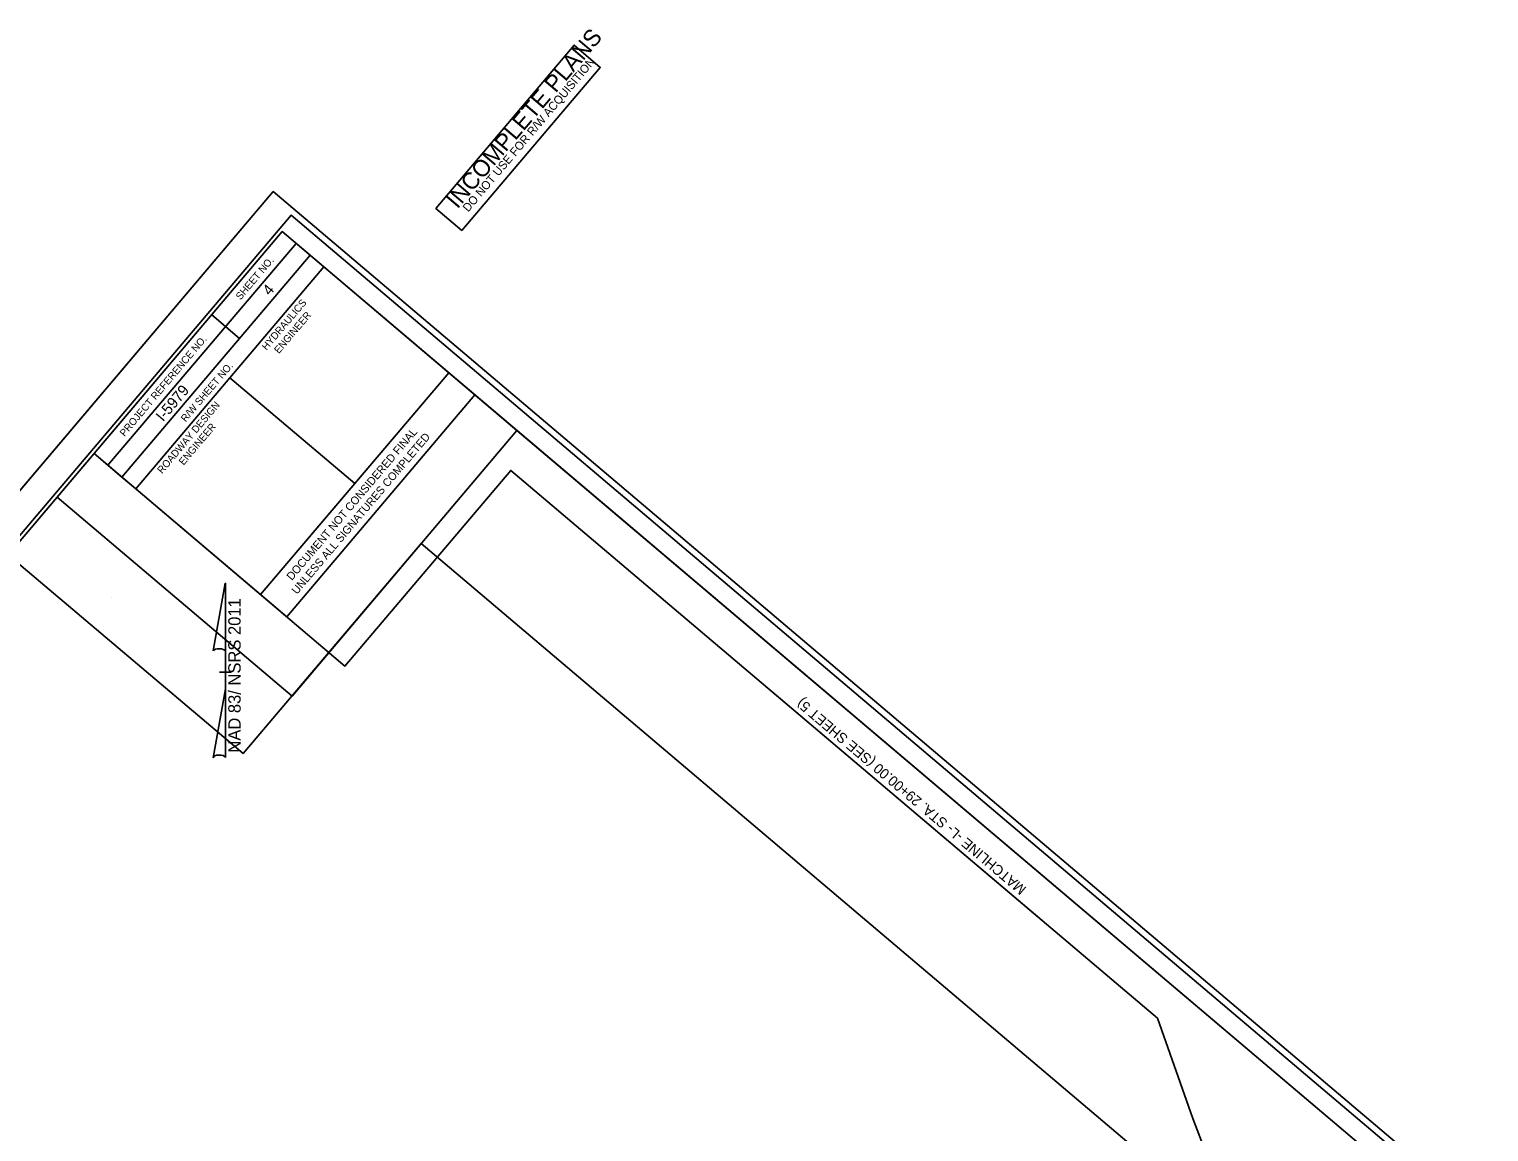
# Model space of a CAD drawing. Extents: x 1761000 to 1762924, y 421789 to 423893.
# Drawn here: x 1761921 to 1762924, y 423135 to 423893 of the extents above; entities that cross this region are included whole.
import ezdxf

# ---------------------------------------------------------------- set-up
doc = ezdxf.new("R2010")
doc.units = 0
for name, color, linetype in [('CTL Primary Horizontal and Vertical Cogo Number', 7, 'Continuous'), ('CTL Sheet Datum Description CELL', 7, 'Continuous'), ('Exist Hydro Stream or Body of Water', 7, 'Continuous'), ('Exist Other Culture Sign Post CELL', 7, 'Continuous'), ('Exist Roads Change in Surface', 7, 'Continuous'), ('Exist Roads Change in Surface Leader', 7, 'Continuous'), ('Exist Roads Change in Surface Text', 7, 'Continuous'), ('Exist Roads Curbs', 7, 'Continuous'), ('Exist Roads Curbs Leader', 7, 'Continuous'), ('Exist Roads EOP', 7, 'Continuous'), ('Exist Roads EOP Other', 7, 'Continuous'), ('Exist Roads EOP Text', 7, 'Continuous'), ('Exist Roads Soil', 7, 'Continuous'), ('Exist Structure Major Deck Tunnel Box Culvert', 7, 'Continuous')]:
    doc.layers.add(name, color=color, linetype=linetype)

msp = doc.modelspace()

# ---------------------------------------------------------------- linework, layer by layer
at = {"layer": 'CTL Primary Horizontal and Vertical Cogo Number'}
msp.add_lwpolyline([(1761925, 421929.5), (1762829.9, 422997.7), (1762190.1, 423539.7), (1762067.8, 423395.3), (1761906.4, 423532), (1761123.8, 422608.2)], close=True, dxfattribs=at)
at = {"layer": 'CTL Sheet Datum Description CELL'}
msp.add_lwpolyline([(1761931.8, 421937.6), (1762821.5, 422987.8), (1762733.1, 423111.6), (1762720.6, 423144.4), (1762696.3, 423213.4), (1762251.7, 423590), (1762137.8, 423455.5), (1761965.3, 423601.6), (1761130.7, 422616.3)], close=True, dxfattribs=at)
at = {"layer": 'Exist Other Culture Sign Post CELL'}
msp.add_line((1762614.2, 423282.9), (1762431.1, 423438.1), dxfattribs=at)
at = {"layer": 'Exist Roads Change in Surface'}
msp.add_lwpolyline([(1761835.8, 421789.4), (1762924, 423073.9), (1762088.5, 423781.7), (1761000.3, 422497.2)], close=True, dxfattribs=at)
at = {"layer": 'Exist Roads Change in Surface Leader'}
msp.add_lwpolyline([(1762218.2, 423754.9), (1762200.3, 423770.1), (1762295.3, 423882.3), (1762313.2, 423867.1)], close=True, dxfattribs=at)
at = {"layer": 'Exist Roads Change in Surface Text'}
msp.add_line((1762088.5, 423781.7), (1761000.3, 422497.2), dxfattribs=at)
at = {"layer": 'Exist Roads Curbs Leader'}
msp.add_line((1761977, 423502.5), (1761977, 423502.5), dxfattribs=at)
at = {"layer": 'Exist Roads EOP'}
for p, q in [((1762079.8, 423504.6), (1762209.1, 423657.2)), ((1762079.8, 423504.6), (1762209.1, 423657.2)), ((1762209.1, 423657.2), (1762227.1, 423642)), ((1762209.1, 423657.2), (1762227.1, 423642)), ((1762227.1, 423642), (1762097.8, 423489.4)), ((1762227.1, 423642), (1762097.8, 423489.4)), ((1762097.8, 423489.4), (1762079.8, 423504.6)), ((1762097.8, 423489.4), (1762079.8, 423504.6))]:
    msp.add_line(p, q, dxfattribs=at)
at = {"layer": 'Exist Roads EOP Other'}
for p, q in [((1761974.9, 423593.5), (1762104.2, 423746.1)), ((1761984.5, 423585.4), (1762113.8, 423738)), ((1761984.5, 423585.4), (1762113.8, 423738)), ((1762046.2, 423696.9), (1762065.3, 423680.8)), ((1762058.7, 423653.6), (1762144.5, 423580.9)), ((1761984.5, 423585.4), (1761994, 423577.3))]:
    msp.add_line(p, q, dxfattribs=at)
for points in [[(1762094.7, 423754.2), (1761125.1, 422609.7), (1761926.2, 421931), (1762895.8, 423075.5)], [(1761965.3, 423601.6), (1762094.7, 423754.2), (1762113.8, 423738), (1761984.5, 423585.4)], [(1762058.7, 423653.6), (1762123.3, 423729.9), (1762209.1, 423657.2), (1762144.5, 423580.9)], [(1761926.2, 421931), (1761125.1, 422609.6), (1761965.3, 423601.6), (1762079.8, 423504.6), (1762209.1, 423657.2), (1762895.8, 423075.5)], [(1761994, 423577.3), (1762058.7, 423653.6), (1762144.5, 423580.9), (1762079.8, 423504.6)]]:
    msp.add_lwpolyline(points, close=True, dxfattribs=at)
at = {"layer": 'Exist Roads EOP Text'}
for p, q in [((1762047.3, 423466), (1762055.5, 423512.4)), ((1762055.6, 423512.4), (1762055.5, 423512.4)), ((1762055.6, 423512.4), (1762055.5, 423512.4)), ((1762055.6, 423512.4), (1762055.6, 423464.6)), ((1762055.6, 423439.8), (1762055.6, 423466)), ((1762055.6, 423464.6), (1762055.6, 423465.9)), ((1762051.6, 423451.4), (1762051.5, 423451.4)), ((1762051.6, 423451.4), (1762059.6, 423451.4)), ((1762055.1, 423451.4), (1762051.6, 423451.4)), ((1762055.6, 423439.8), (1762047.2, 423392.5)), ((1762055.6, 423392.7), (1762055.6, 423439.8))]:
    msp.add_line(p, q, dxfattribs=at)
for centre, start_param, end_param in [((1762051.5, 423465.5), 0.216388, 2.908219), ((1762051.5, 423392.4), 0.201328, 3.141593)]:
    msp.add_ellipse(centre, major_axis=(4.23, -0.03), ratio=0.461098, start_param=start_param, end_param=end_param, dxfattribs=at)
at = {"layer": 'Exist Roads Soil'}
msp.add_lwpolyline([(1761828.9, 421812.2), (1762905.8, 423083.4), (1762100.8, 423765.4), (1761023.9, 422494.2)], close=True, dxfattribs=at)
at = {"layer": 'Exist Structure Major Deck Tunnel Box Culvert'}
for points in [[(1762101.4, 423434.9), (1762256, 423617.5), (1762094.7, 423754.2), (1761940, 423571.6)], [(1761125.1, 422609.6), (1761926.2, 421931), (1762895.8, 423075.5), (1762256, 423617.5), (1762101.4, 423434.9), (1761940, 423571.6)]]:
    msp.add_lwpolyline(points, close=True, dxfattribs=at)

# ---------------------------------------------------------------- texts
at = {"layer": 'Exist Hydro Stream or Body of Water'}
msp.add_text('MATCHLINE -L- STA. 29+00.00 (SEE SHEET 5)', height=7, rotation=139.7301, dxfattribs=at).set_placement((1762606.6, 423303))
at = {"layer": 'Exist Roads Change in Surface Leader'}
for s, height, p in [('INCOMPLETE PLANS', 11.52, (1762215.1, 423769.3)), ('DO NOT USE FOR R/W ACQUISITION', 5.76, (1762222.5, 423767.3))]:
    msp.add_text(s, height=height, rotation=49.7301, dxfattribs=at).set_placement(p)
at = {"layer": 'Exist Roads Curbs'}
for s, p in [('4', (1762086.1, 423709.7)), ('I-5979', (1762012.8, 423623.1))]:
    msp.add_text(s, height=7.5, rotation=49.7301, dxfattribs=at).set_placement(p)
at = {"layer": 'Exist Roads EOP'}
for s, p in [('DOCUMENT NOT CONSIDERED FINAL', (1762101.3, 423514)), ('DOCUMENT NOT CONSIDERED FINAL', (1762101.3, 423514)), ('UNLESS ALL SIGNATURES COMPLETED', (1762104.8, 423504.4)), ('UNLESS ALL SIGNATURES COMPLETED', (1762104.8, 423504.4))]:
    msp.add_text(s, height=5.5, rotation=49.7301, dxfattribs=at).set_placement(p)
at = {"layer": 'Exist Roads EOP Other'}
for s, p in [('SHEET NO.', (1762066, 423706.8)), ('HYDRAULICS', (1762083.9, 423672.2)), ('ENGINEER', (1762092.4, 423669.9)), ('PROJECT REFERENCE NO.', (1761986.3, 423612.9)), ('R/W SHEET NO.', (1762028.3, 423622.9)), ('ROADWAY DESIGN', (1762012.1, 423587.4)), ('ENGINEER', (1762026.9, 423593.2))]:
    msp.add_text(s, height=5, rotation=49.7301, dxfattribs=at).set_placement(p)
at = {"layer": 'Exist Roads EOP Text'}
msp.add_text('NAD 83/ NSRS 2011', height=8.5, rotation=90, dxfattribs=at).set_placement((1762066.1, 423396))

doc.saveas('drawing.dxf')
